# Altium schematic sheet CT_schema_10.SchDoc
size 274 x 160 mm
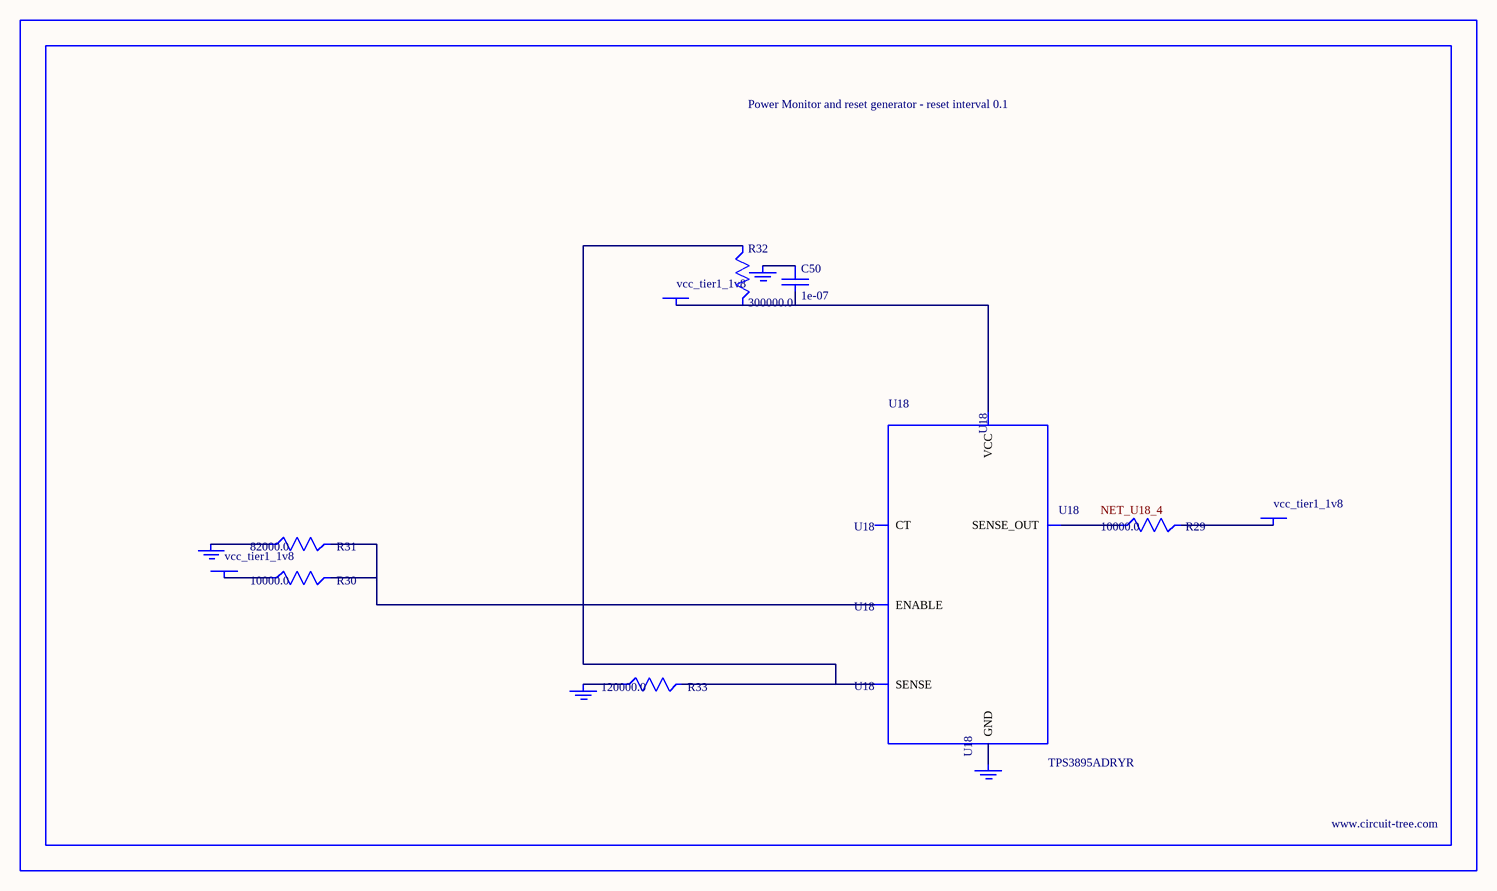
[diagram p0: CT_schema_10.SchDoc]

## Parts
BORDER9  (no value)
C50  1e-07  [C0402]
GND_INSTANCE_9_0  (no value)
GND_INSTANCE_9_1  (no value)
GND_INSTANCE_9_2  (no value)
GND_INSTANCE_9_3  (no value)
POWER_INSTANCE_9_0  vcc_tier1_1v8
POWER_INSTANCE_9_1  vcc_tier1_1v8
POWER_INSTANCE_9_2  vcc_tier1_1v8
R29  10000.0  [R0603]
R30  10000.0  [R0603]
R31  82000.0  [R0603]
R32  300000.0  [R0603]
R33  120000.0  [R0603]
U18  TPS3895ADRYR  [SON-6]

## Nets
NetC50_1: C50.1 GND_INSTANCE_9_2.0(GND)
NetC50_2: C50.2 POWER_INSTANCE_9_2.0(PWR) R32.2 U18.6(VCC)
NetGND_INSTANCE_9_0_0: GND_INSTANCE_9_0.0(GND) R31.1
NetGND_INSTANCE_9_1_0: GND_INSTANCE_9_1.0(GND) R33.1
NetGND_INSTANCE_9_3_0: GND_INSTANCE_9_3.0(GND) U18.2(GND)
NetPOWER_INSTANCE_9_0_0: POWER_INSTANCE_9_0.0(PWR) R30.1
NetPOWER_INSTANCE_9_1_0: POWER_INSTANCE_9_1.0(PWR) R29.2
NetR29_1: R29.1 U18.4(SENSE_OUT)
NetR30_2: R30.2 R31.2 U18.1(ENABLE)
NetR32_1: R32.1 R33.2 U18.3(SENSE)

Not connected (* = marked no-connect by the designer): U18 5(CT)

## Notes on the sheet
- Labels drawn without touching a wire or pin: NET_U18_4

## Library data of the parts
BORDER9 = BORDER_PAGE9
C50 = C0402C104K3RACTU
GND_INSTANCE_9_0-GND_INSTANCE_9_3 = GND
POWER_INSTANCE_9_0-POWER_INSTANCE_9_2 = PWR
R29 R30 = RC0603JR-0710KL
R31 = RC0603JR-0782KL
R32 = RC0603JR-07300KL
R33 = RC0603JR-07120KL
